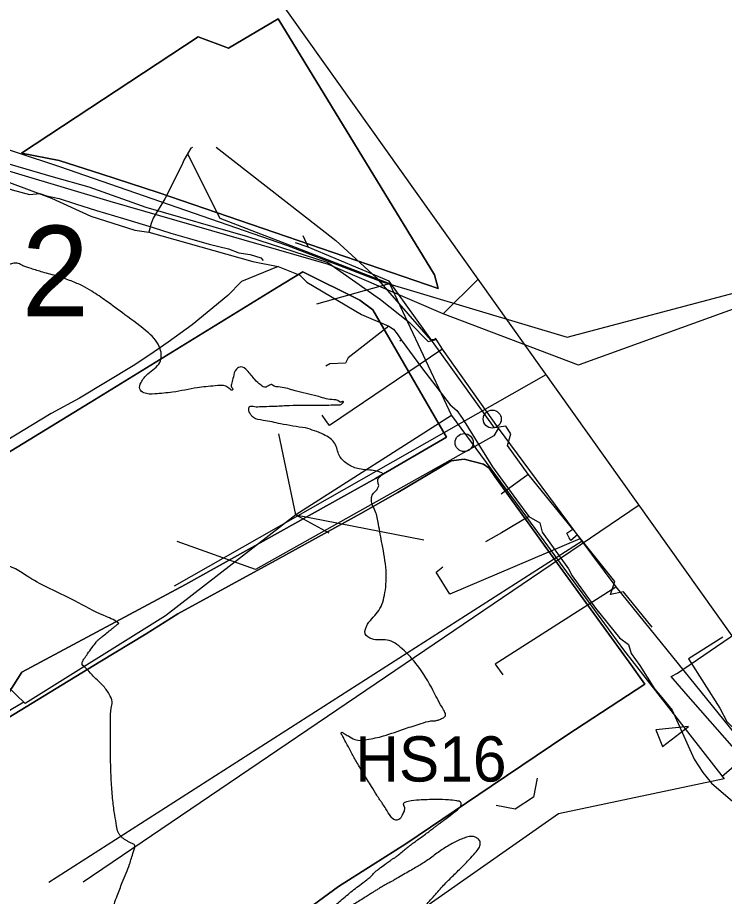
# Model space of a CAD drawing. Extents: x -478645 to -472650, y -1118147 to -1113892.
# Drawn here: x -476908.9 to -476752.6, y -1115675 to -1115480.6 of the extents above; entities that cross this region are included whole.
import ezdxf

# ---------------------------------------------------------------- set-up
doc = ezdxf.new("R2010")
doc.units = 0
for name, color, linetype in [('cestní_příkop', 7, 'Continuous'), ('cesty', 7, 'Continuous'), ('el vedeni _VN', 7, 'Continuous'), ('el vedeni_NN', 7, 'Continuous'), ('el vedeni_NN_podz', 7, 'Continuous'), ('hospodářské sjezdy', 7, 'Continuous'), ('ObPÚ', 7, 'Continuous'), ('plyn_ntl', 7, 'Continuous'), ('plyn_stl', 7, 'Continuous'), ('telekomunikační kabel_O2', 7, 'Continuous'), ('VAK_kanalizace', 7, 'Continuous'), ('VAK_vodovod', 7, 'Continuous'), ('VAK_vodovod_přípojky', 7, 'Continuous'), ('Vrstevnice_vedlejsi', 7, 'Continuous')]:
    doc.layers.add(name, color=color, linetype=linetype)

msp = doc.modelspace()

# ---------------------------------------------------------------- linework, layer by layer
at = {"layer": 'cestní_příkop'}
msp.add_lwpolyline([(-476953.708, -1115504.961), (-476949.454, -1115506.852), (-476939.486, -1115510.147), (-476932.912, -1115512.21), (-476924.05, -1115514.437), (-476917.12, -1115516.344), (-476910.098, -1115518.693), (-476906.231, -1115519.762), (-476903.977, -1115519.501), (-476902.51, -1115520.031), (-476899.669, -1115520.62), (-476896.096, -1115521.799), (-476891.416, -1115523.316), (-476885.489, -1115525.093), (-476878.867, -1115527.076), (-476874.986, -1115528.299), (-476870.901, -1115529.459), (-476866.52, -1115530.758), (-476862.259, -1115531.786), (-476859.956, -1115532.625), (-476857.443, -1115532.998), (-476855.132, -1115533.733), (-476854.612, -1115534.32)], dxfattribs=at)
at = {"layer": 'cesty'}
msp.add_line((-476767.802, -1115638.116), (-476766.323, -1115641.832), dxfattribs=at)
msp.add_lwpolyline([(-476766.323, -1115641.832), (-476760.608, -1115637.405), (-476767.802, -1115638.116)], dxfattribs=at)
for centre in [(-476803.951, -1115569.426), (-476810.159, -1115574.61)]:
    msp.add_circle(centre, 2, dxfattribs=at)
at = {"layer": 'el vedeni _VN'}
for points in [[(-476960.505, -1115493.233), (-476958.229, -1115494.183), (-476899.623, -1115513.536), (-476849.434, -1115530.972), (-476828.522, -1115538.992), (-476787.371, -1115551.336), (-476749.039, -1115541.109), (-476712.836, -1115520.229), (-476674.078, -1115518.099), (-476648.949, -1115510.002), (-476645.065, -1115509.167), (-476610.607, -1115515.405), (-476608.699, -1115515.336)], [(-476752.99, -1115617.645), (-476760.59, -1115622.439), (-476753.68, -1115633.389), (-476752.07, -1115636.279), (-476746.28, -1115641.999), (-476748.07, -1115644.089), (-476753.11, -1115648.49), (-476752.713, -1115648.935)]]:
    msp.add_lwpolyline(points, dxfattribs=at)
at = {"layer": 'el vedeni_NN'}
for p, q in [((-476871.309, -1115510.788), (-476864.181, -1115524.98)), ((-476864.181, -1115524.98), (-476826.67, -1115539.41)), ((-476812.93, -1115568.6), (-476847.382, -1115590.585)), ((-476847.382, -1115590.585), (-476851.156, -1115572.703)), ((-476847.382, -1115590.585), (-476840.104, -1115594.57)), ((-476847.382, -1115590.585), (-476819.057, -1115596.131)), ((-476907.159, -1115632.31), (-476922.078, -1115618.097))]:
    msp.add_line(p, q, dxfattribs=at)
for points in [[(-476842.746, -1115543.945), (-476826.67, -1115539.41), (-476812.925, -1115568.597), (-476794.56, -1115593.64), (-476774.96, -1115620.42), (-476752.697, -1115648.952), (-476789.33, -1115656.72), (-476825.27, -1115681.966), (-476857.812, -1115702.761), (-476874.3, -1115755.055)], [(-476847.382, -1115590.585), (-476876.17, -1115612.946), (-476907.159, -1115632.31)]]:
    msp.add_lwpolyline(points, dxfattribs=at)
at = {"layer": 'el vedeni_NN_podz'}
msp.add_lwpolyline([(-476907.47, -1115632.017), (-476910.352, -1115633.718), (-476921.871, -1115641.567), (-476932.781, -1115648.557), (-476951.241, -1115660.907), (-476975.631, -1115676.477), (-476984.631, -1115682.247), (-476991.301, -1115686.167), (-477009.771, -1115694.657), (-477027.991, -1115700.487), (-477037.641, -1115703.427), (-477045.591, -1115706.477), (-477055.651, -1115711.167)], dxfattribs=at)
at = {"layer": 'hospodářské sjezdy'}
for p, q in [((-476793.987, -1115648.832), (-476794.837, -1115653.012)), ((-476794.837, -1115653.012), (-476798.909, -1115655.711)), ((-476798.909, -1115655.711), (-476803.09, -1115654.866))]:
    msp.add_line(p, q, dxfattribs=at)
at = {"layer": 'ObPÚ'}
for points in [[(-476851.25, -1115480.94), (-476816.69, -1115537.55), (-476815.87, -1115540.54), (-476877.8, -1115519.3), (-476890.27, -1115515.27), (-476899.68, -1115512.27), (-476908, -1115510.64), (-476868.98, -1115484.92), (-476862.26, -1115487.4), (-476851.25, -1115480.94)], [(-476862.26, -1115487.4), (-476868.98, -1115484.92), (-476908, -1115510.64), (-476899.68, -1115512.27), (-476890.27, -1115515.27), (-476877.8, -1115519.3), (-476815.87, -1115540.54), (-476816.69, -1115537.55), (-476851.25, -1115480.94), (-476862.26, -1115487.4)], [(-476845.84, -1115536.82), (-476833.22, -1115543.11), (-476830.32, -1115545.24), (-476814.05, -1115573.4), (-476829.72, -1115582.56), (-476871.77, -1115606.01), (-476907.91, -1115625.37), (-476911.44, -1115631.03), (-476914.68, -1115633.23), (-476935.03, -1115646.22), (-476979.45, -1115674.47), (-476996.82, -1115685.16), (-477019.16, -1115643.09), (-476956.08, -1115604.41), (-476941.69, -1115595.48), (-476928.75, -1115587.71), (-476892.83, -1115565.72), (-476851.64, -1115540.36), (-476845.84, -1115536.82)], [(-476851.64, -1115540.36), (-476892.83, -1115565.72), (-476928.75, -1115587.71), (-476941.69, -1115595.48), (-476956.08, -1115604.41), (-477019.16, -1115643.09), (-476996.82, -1115685.16), (-476979.45, -1115674.47), (-476935.03, -1115646.22), (-476914.68, -1115633.23), (-476911.44, -1115631.03), (-476907.91, -1115625.37), (-476871.77, -1115606.01), (-476829.72, -1115582.56), (-476814.05, -1115573.4), (-476830.32, -1115545.24), (-476833.22, -1115543.11), (-476845.84, -1115536.82), (-476851.64, -1115540.36)], [(-476984.43, -1115683.53), (-476947.85, -1115658.31), (-476916.68, -1115638.92), (-476890.71, -1115623.07), (-476880.46, -1115616.92), (-476873.42, -1115612.49), (-476851.05, -1115600.24), (-476832.98, -1115590.27), (-476824.83, -1115585.68), (-476813.03, -1115578.69), (-476810.14, -1115578.28)], [(-476813.03, -1115578.69), (-476824.83, -1115585.68), (-476832.98, -1115590.27), (-476851.05, -1115600.24), (-476873.42, -1115612.49), (-476880.46, -1115616.92), (-476890.71, -1115623.07), (-476916.68, -1115638.92), (-476947.85, -1115658.31), (-476984.43, -1115683.53)], [(-476810.14, -1115578.28), (-476805.91, -1115579.36), (-476804.65, -1115580.31), (-476803.35, -1115582.14), (-476792.25, -1115597.59), (-476773.71, -1115623.21), (-476770.21, -1115628.06), (-476787.44, -1115639.3), (-476804.2, -1115650.59), (-476823.08, -1115663.32), (-476837.93, -1115672.82), (-476847.08, -1115679.5)], [(-476847.08, -1115679.5), (-476837.93, -1115672.82), (-476823.08, -1115663.32), (-476804.2, -1115650.59), (-476787.44, -1115639.3), (-476770.21, -1115628.06), (-476773.71, -1115623.21), (-476792.25, -1115597.59), (-476803.35, -1115582.14), (-476804.65, -1115580.31), (-476805.91, -1115579.36), (-476810.14, -1115578.28), (-476813.03, -1115578.69)], [(-476742.31, -1115651.59), (-476761.19, -1115630.08), (-476764.44, -1115626.38), (-476763.03, -1115625.58), (-476729.68, -1115602.85)]]:
    msp.add_lwpolyline(points, dxfattribs=at)
at = {"layer": 'plyn_ntl'}
msp.add_line((-476801.947, -1115585.939), (-476796.003, -1115581.607), dxfattribs=at)
msp.add_lwpolyline([(-476768.62, -1115615.425), (-476774.967, -1115607.61), (-476777.83, -1115608.24), (-476776.827, -1115605.311), (-476785.143, -1115595.032), (-476786.55, -1115596.24), (-476786.97, -1115595.69), (-476787.43, -1115594.65), (-476786.145, -1115593.792), (-476796.003, -1115581.607), (-476800.611, -1115575.284), (-476799.879, -1115572.693), (-476800.947, -1115571.002), (-476803.485, -1115571.341), (-476826.742, -1115538.926), (-476844.672, -1115531.409), (-476847.418, -1115530.475)], dxfattribs=at)
at = {"layer": 'plyn_stl'}
msp.add_line((-476845.785, -1115528.839), (-476844.672, -1115531.409), dxfattribs=at)
at = {"layer": 'telekomunikační kabel_O2'}
for points in [[(-476918.03, -1115508.27), (-476915.78, -1115508.87), (-476916.91, -1115513.45), (-476910.67, -1115517.09), (-476901.4, -1115520.57), (-476892.67, -1115524.51), (-476882.95, -1115527.64), (-476879.86, -1115528.08)], [(-476870.23, -1115509.33), (-476870.57, -1115509.54), (-476872.09, -1115512.17), (-476872.55, -1115513.28), (-476876.31, -1115520.7), (-476878.9, -1115525), (-476879.32, -1115526.15), (-476879.86, -1115528.08)], [(-476879.86, -1115528.08), (-476856.87, -1115534.54), (-476851.28, -1115535.67)], [(-476851.28, -1115535.67), (-476859.4, -1115539), (-476862.39, -1115542.12), (-476870.3, -1115548.55), (-476875.6, -1115552.42), (-476879.62, -1115555.24), (-476883.34, -1115557.61), (-476895.15, -1115564.8), (-476901.42, -1115568.22), (-476913.55, -1115575.48), (-476920.8, -1115579.98), (-476922.56, -1115580.99), (-476927.42, -1115584.1), (-476926.94, -1115591.5), (-476926.2, -1115593.91), (-476923.19, -1115599.67), (-476922.63, -1115602.77), (-476922.47, -1115607.58), (-476924.31, -1115609.63)], [(-476851.28, -1115535.67), (-476846.51, -1115537.6), (-476844.92, -1115539.11), (-476832.86, -1115546.28), (-476826.8, -1115548.87)], [(-476826.8, -1115548.87), (-476835.77, -1115555.88), (-476836.41, -1115557.06), (-476839.87, -1115557.18), (-476840.7, -1115557.75)], [(-476826.8, -1115548.87), (-476825.74, -1115549.57), (-476824.95, -1115550.57), (-476824.07, -1115551.87)], [(-476824.36, -1115552.09), (-476824.07, -1115551.87)], [(-476824.07, -1115551.87), (-476819.33, -1115558.28), (-476813.25, -1115566.26), (-476811.76, -1115567.55), (-476810.52, -1115569.32), (-476803.93, -1115579.97), (-476798.57, -1115587.3), (-476795.86, -1115590.93)], [(-476795.86, -1115590.93), (-476801.93, -1115594.61), (-476805.44, -1115596.6)], [(-476795.86, -1115590.93), (-476793.46, -1115592.37), (-476792.94, -1115594.42), (-476787.13, -1115602.51), (-476786.27, -1115604.1), (-476781.16, -1115611.21), (-476775.83, -1115617.77), (-476773.83, -1115619.24), (-476773.21, -1115621.26), (-476771.36, -1115623.91), (-476768.11, -1115629.05), (-476766.84, -1115630.54), (-476764.19, -1115633.77), (-476759.3, -1115644.62), (-476757.44, -1115647.57), (-476755.47, -1115649.96), (-476750.24, -1115654.43), (-476747.33, -1115657.43), (-476738.59, -1115667.17), (-476731.2, -1115676.2), (-476721.89, -1115687.13), (-476720.36, -1115689.36), (-476717.92, -1115694.08)]]:
    msp.add_lwpolyline(points, dxfattribs=at)
at = {"layer": 'VAK_kanalizace'}
msp.add_line((-476874.19, -1115606.312), (-476792.041, -1115559.534), dxfattribs=at)
msp.add_line((-476874.19, -1115606.312), (-476792.041, -1115559.534), dxfattribs=at)
for points in [[(-476807.031, -1115538.469), (-476855.169, -1115470.822)], [(-476888.4, -1115521.316), (-476938.971, -1115506.205)], [(-476814.806, -1115546.167), (-476840.134, -1115535.263), (-476888.4, -1115521.316)], [(-476807.03, -1115538.469), (-476814.806, -1115546.167)], [(-476596.91, -1115841.27), (-476639.491, -1115781.004), (-476677.085, -1115721.078), (-476807.031, -1115538.469)], [(-476736.837, -1115540.074), (-476784.756, -1115557.442)], [(-476784.756, -1115557.442), (-476784.883, -1115557.488), (-476814.806, -1115546.167)], [(-476894.404, -1115671.748), (-476771.514, -1115588.381)]]:
    msp.add_lwpolyline(points, dxfattribs=at)
at = {"layer": 'VAK_vodovod'}
msp.add_line((-476817.589, -1115551.865), (-476816.39, -1115551.679), dxfattribs=at)
for points in [[(-477021.058, -1115400.455), (-477016.816, -1115405.031), (-477008.673, -1115414.809), (-477013.262, -1115419.732), (-477019.005, -1115425.711), (-477022.716, -1115430.367), (-477027.774, -1115435.608), (-477031.941, -1115440.311), (-477041.282, -1115450.653), (-477025.382, -1115464.205), (-477017.113, -1115469.841), (-477002.782, -1115478.162), (-476980.996, -1115489.387), (-476946.256, -1115501.752), (-476917.975, -1115510.877), (-476901.033, -1115515.879), (-476893.13, -1115518.052), (-476880.521, -1115522.577), (-476858.057, -1115529.051), (-476840.282, -1115534.765), (-476828.672, -1115543), (-476822.213, -1115548.077), (-476818.099, -1115552.243)], [(-476864.975, -1115509.265), (-476864.975, -1115509.265), (-476838.514, -1115529.942), (-476829.643, -1115538.117), (-476817.589, -1115551.865)], [(-476818.099, -1115552.243), (-476816.369, -1115551.79), (-476816.319, -1115551.759)], [(-476672.829, -1115728.19), (-476702.929, -1115697.489), (-476776.53, -1115606.54), (-476784.5, -1115595.84), (-476802.579, -1115571.44), (-476814.96, -1115553.93), (-476816.319, -1115551.759), (-476816.39, -1115551.679), (-476816.539, -1115551.549)], [(-476784.06, -1115596.43), (-476901.959, -1115671.923)]]:
    msp.add_lwpolyline(points, dxfattribs=at)
at = {"layer": 'VAK_vodovod_přípojky'}
for points in [[(-476814.96, -1115553.93), (-476815.079, -1115554), (-476839.922, -1115570.86), (-476840.733, -1115569.74), (-476841.563, -1115568.525)], [(-476802.579, -1115571.44), (-476802.679, -1115571.5), (-476803.59, -1115573.139), (-476856.271, -1115602.659), (-476873.588, -1115596.491)], [(-476784.5, -1115595.84), (-476784.599, -1115595.93), (-476813.329, -1115608.129), (-476816.321, -1115603.263), (-476814.891, -1115602.115)], [(-476776.53, -1115606.54), (-476776.63, -1115606.59), (-476803.27, -1115623.657), (-476801.625, -1115625.953)]]:
    msp.add_lwpolyline(points, dxfattribs=at)
at = {"layer": 'Vrstevnice_vedlejsi'}
for points in [[(-476845.231, -1115571.374), (-476850.742, -1115570.468), (-476854.578, -1115569.699), (-476856.739, -1115569.066), (-476857.224, -1115568.568), (-476857.558, -1115568.055), (-476857.741, -1115567.527), (-476857.772, -1115566.982), (-476857.577, -1115566.653), (-476857.156, -1115566.538), (-476856.509, -1115566.639), (-476855.022, -1115566.654), (-476852.696, -1115566.585), (-476849.529, -1115566.431), (-476846.448, -1115566.34), (-476843.452, -1115566.313), (-476840.542, -1115566.348), (-476838.492, -1115566.284), (-476837.303, -1115566.12), (-476836.976, -1115565.856), (-476836.818, -1115565.676), (-476836.832, -1115565.58), (-476837.015, -1115565.568), (-476837.171, -1115565.58), (-476837.3, -1115565.615), (-476837.401, -1115565.673), (-476837.475, -1115565.705), (-476837.523, -1115565.713), (-476837.544, -1115565.695), (-476837.564, -1115565.679), (-476837.582, -1115565.667), (-476837.6, -1115565.657), (-476837.621, -1115565.645), (-476837.644, -1115565.63), (-476837.67, -1115565.613), (-476837.698, -1115565.59), (-476837.73, -1115565.562), (-476837.764, -1115565.529), (-476839.409, -1115565.119), (-476842.665, -1115564.332), (-476847.533, -1115563.167), (-476850.822, -1115562.357), (-476852.533, -1115561.902), (-476852.666, -1115561.801), (-476852.966, -1115561.85), (-476853.433, -1115562.047), (-476854.066, -1115562.393), (-476855.059, -1115561.943), (-476856.412, -1115560.696), (-476858.123, -1115558.651), (-476859.488, -1115557.869), (-476860.506, -1115558.35), (-476861.178, -1115560.092), (-476861.532, -1115561.429), (-476861.57, -1115562.36), (-476861.29, -1115562.886), (-476861.403, -1115563.028), (-476861.908, -1115562.787), (-476862.805, -1115562.161), (-476865.22, -1115562.067), (-476869.154, -1115562.506), (-476874.605, -1115563.476), (-476878.541, -1115563.841), (-476880.963, -1115563.602), (-476881.871, -1115562.758), (-476881.58, -1115561.356), (-476880.09, -1115559.397), (-476877.401, -1115556.88), (-476877.349, -1115553.865), (-476879.934, -1115550.352), (-476885.155, -1115546.341), (-476889.327, -1115543.275), (-476892.448, -1115541.155), (-476894.519, -1115539.98), (-476897.02, -1115538.882), (-476899.952, -1115537.863), (-476903.316, -1115536.922), (-476905.897, -1115536.135), (-476907.696, -1115535.502), (-476908.714, -1115535.023), (-476909.72, -1115534.963), (-476910.716, -1115535.321), (-476911.701, -1115536.098), (-476913.17, -1115536.058), (-476915.124, -1115535.201), (-476917.562, -1115533.526), (-476919.995, -1115532.102), (-476922.422, -1115530.929), (-476924.844, -1115530.005), (-476927.352, -1115528.569), (-476929.947, -1115526.618), (-476932.629, -1115524.155), (-476935.985, -1115522.105), (-476940.016, -1115520.468), (-476944.721, -1115519.245), (-476948.294, -1115518.392), (-476950.732, -1115517.909)], [(-476824.38, -1115665.556), (-476823.385, -1115664.724), (-476822.641, -1115664.111), (-476822.149, -1115663.717), (-476821.908, -1115663.543), (-476821.341, -1115663.132), (-476820.449, -1115662.484), (-476819.231, -1115661.6), (-476818.198, -1115660.836), (-476817.352, -1115660.194), (-476816.691, -1115659.672), (-476816.115, -1115659.23), (-476815.625, -1115658.867), (-476815.221, -1115658.583), (-476814.421, -1115657.981), (-476813.226, -1115657.059), (-476811.635, -1115655.819), (-476810.864, -1115654.87), (-476810.913, -1115654.211), (-476811.782, -1115653.842), (-476813.607, -1115653.628), (-476816.388, -1115653.57), (-476820.125, -1115653.668), (-476822.534, -1115653.99), (-476823.616, -1115654.535), (-476823.37, -1115655.304), (-476823.453, -1115656.135), (-476823.866, -1115657.027), (-476824.608, -1115657.982), (-476825.453, -1115658.068), (-476826.402, -1115657.287), (-476827.455, -1115655.638), (-476828.2, -1115654.484), (-476828.64, -1115653.824), (-476828.772, -1115653.659), (-476829.44, -1115652.606), (-476830.642, -1115650.667), (-476832.379, -1115647.839), (-476833.85, -1115645.364), (-476835.055, -1115643.242), (-476835.993, -1115641.473), (-476836.665, -1115640.214), (-476837.071, -1115639.466), (-476837.21, -1115639.23), (-476837.306, -1115639.055), (-476837.356, -1115638.943), (-476837.363, -1115638.893), (-476837.35, -1115638.837), (-476837.318, -1115638.776), (-476837.266, -1115638.709), (-476836.744, -1115638.941), (-476835.752, -1115639.474), (-476834.289, -1115640.305), (-476831.702, -1115640.314), (-476827.992, -1115639.499), (-476823.157, -1115637.861), (-476819.665, -1115636.758), (-476817.518, -1115636.189), (-476816.714, -1115636.154), (-476815.929, -1115635.983), (-476815.162, -1115635.675), (-476814.413, -1115635.231), (-476815.044, -1115633.126), (-476817.056, -1115629.362), (-476820.448, -1115623.938), (-476823.833, -1115620.245), (-476827.211, -1115618.283), (-476830.581, -1115618.053), (-476832.007, -1115616.891), (-476831.488, -1115614.796), (-476829.026, -1115611.768), (-476827.672, -1115607.806), (-476827.426, -1115602.908), (-476828.29, -1115597.076), (-476829.083, -1115592.697), (-476829.806, -1115589.772), (-476830.458, -1115588.3), (-476830.65, -1115587.06), (-476830.381, -1115586.05), (-476829.651, -1115585.271), (-476829.204, -1115584.62), (-476829.039, -1115584.097), (-476829.157, -1115583.701), (-476829.228, -1115583.345), (-476829.253, -1115583.03), (-476829.232, -1115582.755), (-476829.04, -1115582.419), (-476828.677, -1115582.022), (-476828.145, -1115581.563), (-476828.808, -1115581.134), (-476830.666, -1115580.735), (-476833.719, -1115580.367), (-476836.082, -1115579.263), (-476837.755, -1115577.425), (-476838.737, -1115574.852), (-476841.229, -1115572.835), (-476845.231, -1115571.374)], [(-476897.933, -1115718.027), (-476897.079, -1115717.536), (-476896.19, -1115716.945), (-476895.267, -1115716.254), (-476894.308, -1115715.461), (-476893.528, -1115714.807), (-476892.925, -1115714.29), (-476892.501, -1115713.911), (-476891.842, -1115713.363), (-476890.948, -1115712.645), (-476889.819, -1115711.758), (-476889.001, -1115711.065), (-476888.494, -1115710.568), (-476888.297, -1115710.265), (-476887.89, -1115709.702), (-476887.273, -1115708.878), (-476886.446, -1115707.795), (-476885.543, -1115706.733), (-476884.565, -1115705.693), (-476883.511, -1115704.674), (-476882.856, -1115703.931), (-476882.601, -1115703.462), (-476882.745, -1115703.268), (-476882.933, -1115703.071), (-476883.167, -1115702.871), (-476883.446, -1115702.668), (-476884.012, -1115701.216), (-476884.864, -1115698.515), (-476886.003, -1115694.564), (-476886.871, -1115690.623), (-476887.466, -1115686.694), (-476887.791, -1115682.776), (-476887.955, -1115680.06), (-476887.958, -1115678.546), (-476887.801, -1115678.234), (-476887.664, -1115677.808), (-476887.545, -1115677.267), (-476887.446, -1115676.613), (-476886.841, -1115674.829), (-476885.729, -1115671.915), (-476884.112, -1115667.871), (-476883.241, -1115665.073), (-476883.116, -1115663.522), (-476883.738, -1115663.216), (-476884.338, -1115662.894), (-476884.915, -1115662.556), (-476885.47, -1115662.201), (-476885.941, -1115661.788), (-476886.329, -1115661.319), (-476886.633, -1115660.792), (-476886.981, -1115659.36), (-476887.374, -1115657.022), (-476887.811, -1115653.779), (-476888.117, -1115649.865), (-476888.292, -1115645.281), (-476888.337, -1115640.026), (-476888.299, -1115636.054), (-476888.178, -1115633.363), (-476887.975, -1115631.955), (-476888.612, -1115630.256), (-476890.089, -1115628.268), (-476892.405, -1115625.99), (-476893.917, -1115624.364), (-476894.625, -1115623.391), (-476894.53, -1115623.07), (-476894.126, -1115622.388), (-476893.414, -1115621.345), (-476892.393, -1115619.941), (-476891.638, -1115618.945), (-476891.151, -1115618.357), (-476890.931, -1115618.178), (-476890.431, -1115617.768), (-476889.65, -1115617.13), (-476888.589, -1115616.261), (-476887.765, -1115615.592), (-476887.179, -1115615.122), (-476886.831, -1115614.852), (-476886.605, -1115614.671), (-476886.502, -1115614.58), (-476886.521, -1115614.579), (-476886.55, -1115614.566), (-476886.588, -1115614.539), (-476886.635, -1115614.5), (-476889.833, -1115612.867), (-476896.18, -1115609.64), (-476905.679, -1115604.82), (-476912.031, -1115601.423), (-476915.237, -1115599.447), (-476915.297, -1115598.895), (-476915.638, -1115598.439), (-476916.261, -1115598.08), (-476917.165, -1115597.818), (-476918.553, -1115596.277), (-476920.425, -1115593.458), (-476922.781, -1115589.36), (-476924.649, -1115586.554), (-476926.031, -1115585.04)], [(-476816.714, -1115768.022), (-476817.798, -1115766.771), (-476818.46, -1115765.324), (-476818.699, -1115763.68), (-476818.516, -1115761.84), (-476818.683, -1115758.495), (-476819.2, -1115753.644), (-476820.067, -1115747.289), (-476821.379, -1115740.726), (-476823.137, -1115733.956), (-476825.34, -1115726.978), (-476826.18, -1115719.347), (-476825.656, -1115711.064), (-476823.768, -1115702.128), (-476822.479, -1115694.786), (-476821.79, -1115689.037), (-476821.701, -1115684.882), (-476820.967, -1115681.282), (-476819.589, -1115678.235), (-476817.566, -1115675.743), (-476815.49, -1115673.378), (-476813.361, -1115671.139), (-476811.179, -1115669.026), (-476809.402, -1115667.223), (-476808.03, -1115665.73), (-476807.064, -1115664.545), (-476806.624, -1115663.541), (-476806.71, -1115662.717), (-476807.321, -1115662.072), (-476808.099, -1115661.751), (-476809.043, -1115661.754), (-476810.153, -1115662.081), (-476811.314, -1115662.54), (-476812.525, -1115663.132), (-476813.787, -1115663.858), (-476815.008, -1115664.631), (-476816.19, -1115665.451), (-476817.331, -1115666.319), (-476818.449, -1115667.106), (-476819.544, -1115667.813), (-476820.615, -1115668.439), (-476821.826, -1115669.147), (-476823.177, -1115669.937), (-476824.668, -1115670.807), (-476825.728, -1115671.416), (-476826.358, -1115671.762), (-476826.557, -1115671.845), (-476826.972, -1115672.068), (-476827.605, -1115672.431), (-476828.454, -1115672.932), (-476829.216, -1115673.393), (-476829.891, -1115673.813), (-476830.479, -1115674.192), (-476831.276, -1115674.696), (-476832.281, -1115675.326), (-476833.494, -1115676.082), (-476834.729, -1115676.851), (-476835.983, -1115677.632), (-476837.258, -1115678.426), (-476838.403, -1115679.132), (-476839.418, -1115679.75), (-476840.303, -1115680.281), (-476841.1, -1115680.768), (-476841.806, -1115681.213), (-476842.424, -1115681.616), (-476842.953, -1115681.943), (-476843.394, -1115682.194), (-476843.746, -1115682.371), (-476845.065, -1115683.141), (-476847.352, -1115684.506), (-476850.607, -1115686.464), (-476851.773, -1115686.981), (-476850.851, -1115686.056), (-476847.841, -1115683.689), (-476845.502, -1115681.895), (-476843.834, -1115680.675), (-476842.838, -1115680.028), (-476841.826, -1115679.329), (-476840.798, -1115678.577), (-476839.754, -1115677.773), (-476838.631, -1115676.874), (-476837.431, -1115675.882), (-476836.152, -1115674.795), (-476834.855, -1115673.74), (-476833.539, -1115672.716), (-476832.205, -1115671.723), (-476831.207, -1115670.927), (-476830.544, -1115670.33), (-476830.216, -1115669.929), (-476829.575, -1115669.352), (-476828.62, -1115668.598), (-476827.351, -1115667.666), (-476826.426, -1115667.007), (-476825.846, -1115666.62), (-476825.611, -1115666.504), (-476825.122, -1115666.15), (-476824.38, -1115665.556)]]:
    msp.add_spline(points, degree=3, dxfattribs=at)

# ---------------------------------------------------------------- texts
at = {"layer": 'cesty'}
msp.add_text('MK 2', height=20, rotation=359.99999, dxfattribs=at).set_placement((-476955.5, -1115546.662))
at = {"layer": 'hospodářské sjezdy'}
msp.add_text('HS16', height=10, rotation=359.99999, dxfattribs=at).set_placement((-476834.236, -1115649.579))

doc.saveas('drawing.dxf')
